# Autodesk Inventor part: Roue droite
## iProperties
Author: Flavien MARTY
Shininess: 41.0
PropertySet Name: _Private Model Information
Created: 2001-10
Part Number: Roue droite
Material: Par défaut
Document SubType Name: Modélisation
Designer: Flavien MARTY
Control State: 0
Master: False
Checked Out: False
PropertySet Name: Design Tracking Control
Density: 0.0
Volumn: 0.0
Area: 0.0
PropertySet Name: Model Information
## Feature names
1. Base1
